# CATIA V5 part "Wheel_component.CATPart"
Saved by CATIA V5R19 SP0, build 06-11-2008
Part number: Wheel_component
Revision: ANY
Definition: UNKNOWN
Nomenclature: Wheel_component
Source: Unknown
Bounding box of the stored display mesh (mm): x -10 to 35, y -104.812 to 10, z -55 to 55
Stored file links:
  C:\Users\b2l\Desktop\CATIA V5R19\E1 - Assembly (Connecting Rod Assy)\Step 1\Wheel_component.CATPart
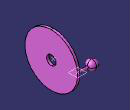
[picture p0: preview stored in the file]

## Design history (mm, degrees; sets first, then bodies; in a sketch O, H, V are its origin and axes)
DatumSurface1 to DatumSurface10
Solid1: solid without history
DatumCurve1
Set1
  DatumCurve2
  Point1: type Center, Curve edge [face of Solid1 | face of Solid1]
  DatumSurface11
  Point2: type Center, Curve edge [face of Solid1 | face of Solid1]
  Point3: type Center, Curve DatumCurve3
  DatumCurve3
  Line1: type PtPt, SecondPoint Point1, FirstPoint Point3
  Plane1: type 1Line1Pt, Line Line1, RefPoint Point2
  Plane2: type OffsetPt, RefPlane Plane1, RefPoint Point1
  Plane3: type Normal, Curve edge [face of Solid1 | face of Solid1], RefPoint Point2
Body1 "Extrude1" (main body)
